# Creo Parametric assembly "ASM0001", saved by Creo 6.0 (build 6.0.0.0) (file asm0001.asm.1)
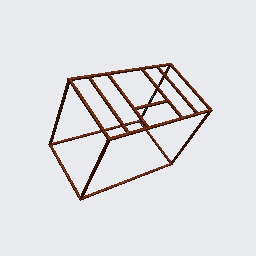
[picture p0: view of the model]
Units: millimeter Newton Second (mmNs); MM, TONNE, SECS

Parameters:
  PROJECT_SHORT = "3"
  JOINT_4 = "GEHRUNG 1_91 START_SURFACE 1_161 END_SURFACE"
  JOINT_6 = "GEHRUNG 1_71 END_SURFACE 1_91 END_SURFACE"
  JOINT_8 = "GEHRUNG 1_151 START_SURFACE 1_71 START_SURFACE"
  JOINT_10 = "GEHRUNG 1_121 START_SURFACE 1_51 END_SURFACE"
  JOINT_12 = "GEHRUNG 1_121 END_SURFACE 1_131 START_SURFACE"
  JOINT_14 = "GEHRUNG 1_131 END_SURFACE 1_111 START_SURFACE"
  JOINT_16 = "GEHRUNG 1_51 START_SURFACE 1_111 END_SURFACE"

Other parameters: PROFILE_NUMBER, JOINT_NUMBER

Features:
  1. datum plane "ASM_RIGHT"
  2. datum plane "ASM_TOP"
  3. datum plane "ASM_FRONT"
  4. coordinate system
  5. component "FRAME"
  6. datum point "APNT0"
  7. coordinate system
  8. coordinate system
  9. datum point "APNT1"
  10. component "3_SQUARE_TUBE_1"
  11. datum point "APNT2"
  12. coordinate system
  13. coordinate system
  14. datum point "APNT3"
  15. component "3_SQUARE_TUBE_2"
  16. datum point "APNT4"
  17. coordinate system
  18. coordinate system
  19. datum point "APNT5"
  20. component "3_SQUARE_TUBE_3"
  21. datum point "APNT6"
  22. coordinate system
  23. coordinate system
  24. datum point "APNT7"
  25. component "3_SQUARE_TUBE_4"
  26. datum point "APNT8"
  27. coordinate system
  28. coordinate system
  29. datum point "APNT9"
  30. component "3_SQUARE_TUBE_5"
  31. datum point "APNT10"
  32. coordinate system
  33. coordinate system
  34. datum point "APNT11"
  35. component "3_SQUARE_TUBE_6"
  36. datum point "APNT12"
  37. coordinate system
  38. coordinate system
  39. datum point "APNT13"
  40. component "3_SQUARE_TUBE_7"
  41. group "PROFIL_REF_CSYS_7"
  42. datum point "APNT14"
  43. coordinate system "ACS14"
  44. coordinate system "ACS15"
  45. datum point "APNT15"
  46. component "3_SQUARE_TUBE_8"
  47. group "PROFIL_REF_CSYS_8"
  48. datum point "APNT16"
  49. coordinate system "ACS16"
  50. coordinate system "ACS17"
  51. datum point "APNT17"
  52. component "3_SQUARE_TUBE_9"
  53. group "PROFIL_REF_CSYS_9"
  54. datum point "APNT18"
  55. coordinate system "ACS18"
  56. coordinate system "ACS19"
  57. datum point "APNT19"
  58. component "3_SQUARE_TUBE_10"
  59. group "PROFIL_REF_CSYS_10"
  60. datum point "APNT20"
  61. coordinate system "ACS20"
  62. coordinate system "ACS21"
  63. datum point "APNT21"
  64. component "3_SQUARE_TUBE_11"
  65. group "PROFIL_REF_CSYS_11"
  66. datum point "APNT22"
  67. coordinate system "ACS22"
  68. coordinate system "ACS23"
  69. datum point "APNT23"
  70. component "3_SQUARE_TUBE_12"
  71. group "PROFIL_REF_CSYS_12"
  72. datum point "APNT24"
  73. coordinate system "ACS24"
  74. coordinate system "ACS25"
  75. datum point "APNT25"
  76. component "3_SQUARE_TUBE_13"
  77. group "PROFIL_REF_CSYS_13"
  78. datum point "APNT26"
  79. coordinate system "ACS26"
  80. coordinate system "ACS27"
  81. datum point "APNT27"
  82. component "3_SQUARE_TUBE_14"
  83. group "PROFIL_REF_CSYS_14"
  84. datum point "APNT28"
  85. coordinate system "ACS28"
  86. coordinate system "ACS29"
  87. datum point "APNT29"
  88. component "3_SQUARE_TUBE_15"
  89. group "PROFIL_REF_CSYS_15"
  90. datum point "APNT30"
  91. coordinate system "ACS30"
  92. coordinate system "ACS31"
  93. datum point "APNT31"
  94. component "3_SQUARE_TUBE_16"
  95. group "PROFIL_REF_CSYS_16"
  96. datum point "APNT32"
  97. coordinate system "ACS32"
  98. coordinate system "ACS33"
  99. datum point "APNT33"
  100. component "3_SQUARE_TUBE_17"

Other named items: PROFIL_REF_CSYS, PROFIL_REF_CSYS_1, PROFIL_REF_CSYS_2, PROFIL_REF_CSYS_3, PROFIL_REF_CSYS_4, PROFIL_REF_CSYS_5, PROFIL_REF_CSYS_6, ACS0, ACS1, ACS2, ACS3, ACS4, ACS5, ACS6, ACS7, ACS8, ACS9, ACS10, ACS11, ACS12, ACS13

Named dimensions: T_PARAM, X_ROT, Z_ROT, X_OFF, Y_OFF, Z_OFF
